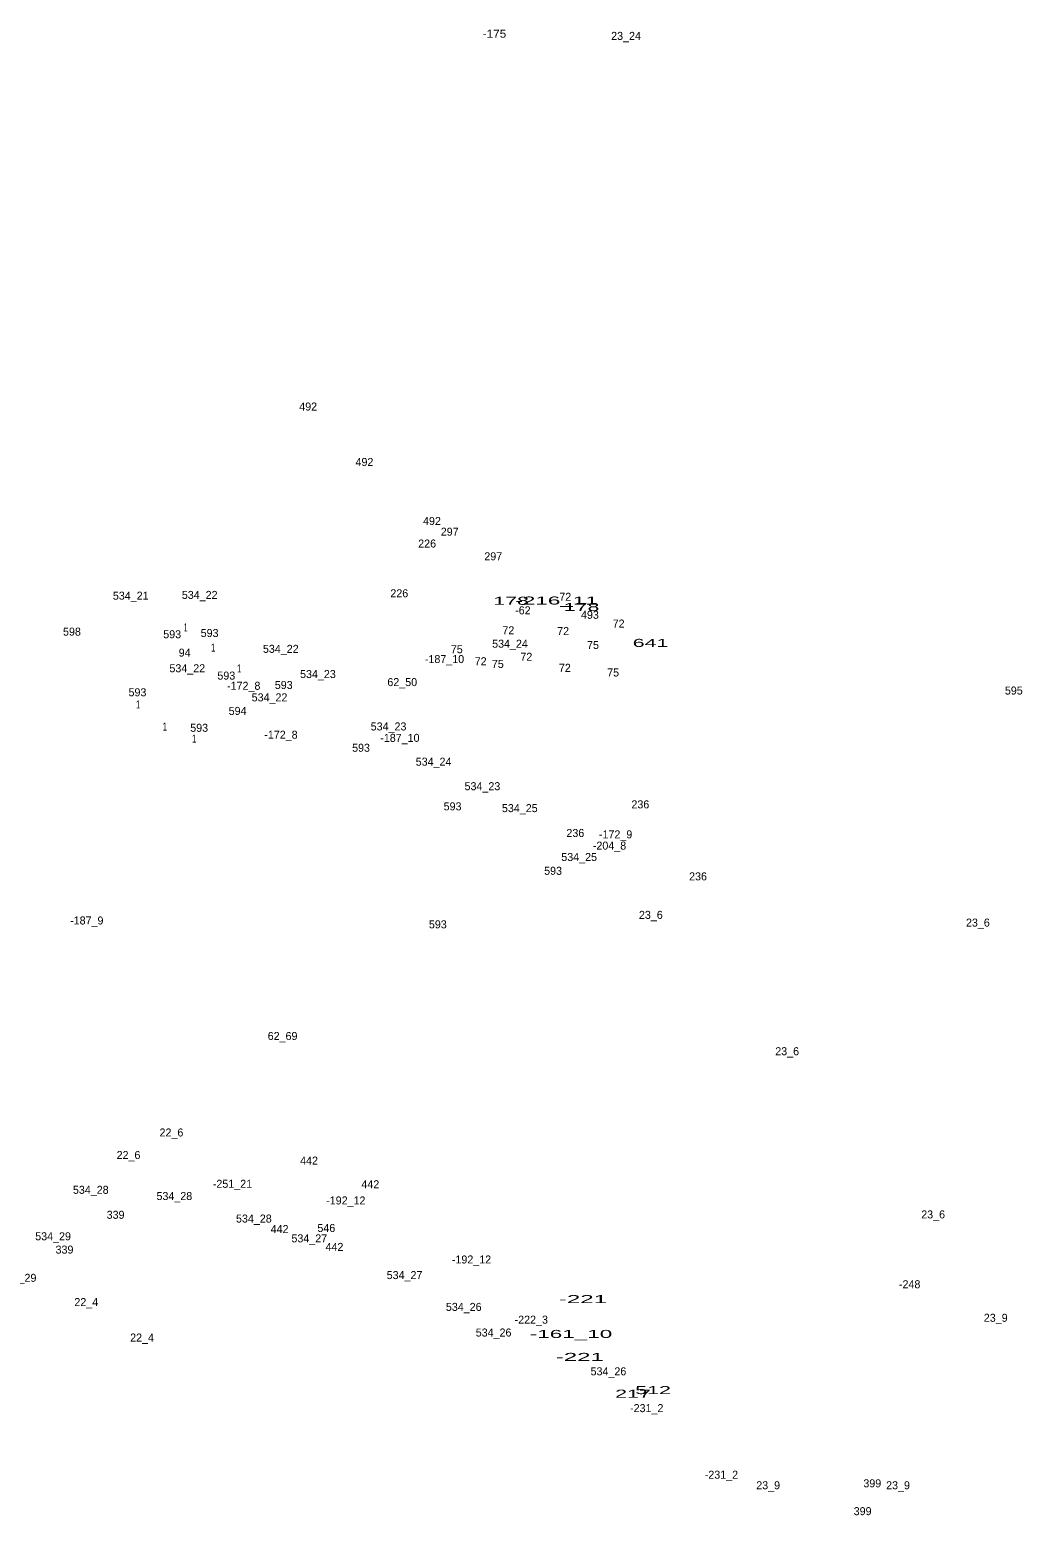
# Model space of a CAD drawing. Extents: x -661742 to -657295, y -1002932 to -996888.
# Drawn here: x -659315 to -658819, y -999837 to -999095 of the extents above; entities that cross this region are included whole.
import ezdxf
from ezdxf.enums import TextEntityAlignment as Align

# ---------------------------------------------------------------- set-up
doc = ezdxf.new("R2010")
doc.units = 0
doc.header["$LTSCALE"] = 1.6
doc.layers.add('24', color=7, linetype='Continuous')

msp = doc.modelspace()

# ---------------------------------------------------------------- texts
at = {"layer": '24'}
for s, width, p in [('-175', 1.1, (-659083.2, -999099.1)), ('178', 2, (-659074.863, -999382.49)), ('-216_11', 2.1, (-659052.139, -999382.36)), ('178', 2, (-659039.673, -999385.58)), ('1', 0.65, (-659237.497, -999395.79)), ('1', 0.65, (-659223.767, -999405.85)), ('641', 2, (-659005.178, -999403.52)), ('1', 0.65, (-659210.807, -999416.3)), ('1', 0.65, (-659261.287, -999434.29)), ('1', 0.65, (-659247.937, -999445.32)), ('1', 0.65, (-659233.247, -999451.32)), ('-221', 2.25, (-659038.961, -999731.43)), ('-161_10', 2.1, (-659044.945, -999748.84)), ('-221', 2.25, (-659040.511, -999760.33)), ('217', 2, (-659013.973, -999778.71)), ('512', 2, (-659003.927, -999776.9))]:
    msp.add_text(s, height=4, dxfattribs=dict(at, width=width)).set_placement(p, align=Align.CENTER)
for s, p in [('23_24', (-659017.43, -999100.18)), ('492', (-659176.287, -999285.4)), ('492', (-659148.177, -999313.13)), ('492', (-659114.437, -999342.59)), ('297', (-659105.558, -999347.95)), ('226', (-659116.843, -999353.87)), ('297', (-659083.798, -999360.24)), ('534_21', (-659264.973, -999379.92)), ('534_22', (-659230.5, -999379.54)), ('226', (-659130.763, -999378.73)), ('72', (-659047.823, -999380.48)), ('-62', (-659069, -999387.25)), ('493', (-659035.487, -999389.48)), ('598', (-659294.343, -999397.89)), ('593', (-659244.253, -999399.2)), ('593', (-659225.543, -999398.57)), ('72', (-659076.253, -999397.21)), ('72', (-659048.883, -999397.6)), ('72', (-659021.133, -999393.83)), ('534_22', (-659189.98, -999406.49)), ('75', (-659102.023, -999406.69)), ('534_24', (-659075.434, -999403.93)), ('75', (-659033.943, -999404.56)), ('94', (-659238.017, -999408.38)), ('-187_10', (-659108.159, -999411.6)), ('72', (-659090.083, -999412.69)), ('75', (-659081.523, -999414.04)), ('72', (-659067.263, -999410.47)), ('534_22', (-659236.7, -999416.19)), ('593', (-659217.203, -999419.86)), ('534_23', (-659171.41, -999419.08)), ('72', (-659048.013, -999415.98)), ('75', (-659023.893, -999418.3)), ('593', (-659261.603, -999428.2)), ('-172_8', (-659208.502, -999424.96)), ('593', (-659188.513, -999424.56)), ('62_50', (-659129.284, -999423.11)), ('595', (-658823.653, -999427.32)), ('594', (-659211.557, -999437.52)), ('534_22', (-659195.6, -999430.74)), ('593', (-659230.773, -999445.94)), ('-172_8', (-659189.892, -999449.39)), ('534_23', (-659136.12, -999445.26)), ('-187_10', (-659130.449, -999450.97)), ('593', (-659149.873, -999455.92)), ('534_24', (-659113.624, -999462.88)), ('534_23', (-659089.21, -999475.13)), ('593', (-659104.123, -999485.2)), ('534_25', (-659070.53, -999486.08)), ('236', (-659010.283, -999484.21)), ('236', (-659042.773, -999498.52)), ('-172_9', (-659022.647, -999499.2)), ('534_25', (-659040.87, -999510.51)), ('-204_8', (-659025.701, -999504.82)), ('593', (-659053.913, -999517.4)), ('236', (-658981.463, -999520.19)), ('23_6', (-659005.04, -999539.43)), ('-187_9', (-659286.927, -999542.23)), ('593', (-659111.493, -999544.16)), ('23_6', (-658841.61, -999543.29)), ('62_69', (-659189.081, -999599.96)), ('23_6', (-658936.92, -999607.57)), ('22_6', (-659244.62, -999648.17)), ('22_6', (-659266.08, -999659.44)), ('442', (-659175.846, -999662.2)), ('-251_21', (-659214.119, -999673.82)), ('442', (-659145.216, -999674.03)), ('534_28', (-659284.93, -999676.83)), ('534_28', (-659243.17, -999679.93)), ('-192_12', (-659157.485, -999682.14)), ('339', (-659272.533, -999689.3)), ('23_6', (-658863.97, -999689.12)), ('534_28', (-659203.43, -999691.18)), ('442', (-659190.576, -999696.43)), ('546', (-659167.217, -999695.9)), ('534_29', (-659303.774, -999700.04)), ('534_27', (-659175.725, -999701.07)), ('339', (-659298.063, -999706.7)), ('442', (-659163.146, -999705.35)), ('-192_12', (-659094.665, -999711.64)), ('534_27', (-659128.125, -999719.43)), ('534_29', (-659321.034, -999720.79)), ('-248', (-658875.699, -999724.01)), ('22_4', (-659287.18, -999732.94)), ('534_26', (-659098.544, -999735.33)), ('-222_3', (-659064.802, -999741.71)), ('23_9', (-658832.7, -999740.76)), ('534_26', (-659083.624, -999748.13)), ('22_4', (-659259.29, -999750.65)), ('534_26', (-659026.234, -999767.52)), ('-231_2', (-659007.106, -999785.91)), ('-231_2', (-658969.776, -999819.19)), ('399', (-658894.378, -999823.48)), ('23_9', (-658946.41, -999824.46)), ('23_9', (-658881.51, -999824.46)), ('399', (-658899.208, -999837.41))]:
    msp.add_text(s, height=4, dxfattribs=at).set_placement(p, align=Align.CENTER)

doc.saveas('drawing.dxf')
